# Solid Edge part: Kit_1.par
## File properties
Sűrűség: 0,000 kg/m^3
Pontosság: 0,990
Author: ahadarics
Last saved by: ahadarics
Revision: 76
Username: ahadarics
Dokumentum tartalom típus: 0
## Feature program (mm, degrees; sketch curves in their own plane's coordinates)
base feature "unnamed BaseFeature 1"
thread "unnamed Thread 1"
chamfer "unnamed Chamfer 1"
sketch for "Furat_1" plane through (0, -48.5, 12) normal (0, 0, 1) x-axis (0, 1, 0)
hole "Furat_1" diameter 9.728 finite  ThreadDepth = 7.5 mm
chamfer "Letörés_2" setback 0.7
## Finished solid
Body 1: solid body, 75 faces, 111 edges, 38 vertices, 5 internal voids.
  Faces by surface: plane 27, cone 23, cylinder 20, torus 5
  Edges by curve: circle 67, line 28, spline 12, intersection 4
Bounding box of the edges (mm; curved faces can reach further): 26.800 x 43.000 x 25.400, from (-13.4, -76.25, -13.4) to (13.4, -33.25, 12).
Cylindrical faces by radius (mm): R4 x1, R4.15 x1, R4.28 x1, R4.283 x1, R5.25 x1, R5.55 x1, R6 x2, R7.05 x3, R8.05 x1, R8.1 x1, R8.95 x1, R9.85 x1, R10 x1, R11 x2, R11.1 x1, R13.4 x1
Conical faces (half-angle, radius in mm at the cone's reference point): 0.1788 deg R6.7706 x1, 17.2279 deg R5.55 x1, 19.7315 deg R5.0176 x1, 20 deg R5.909 x2, 21.5244 deg R6.2703 x1, 30 deg R9.9134 x1, 45 deg R4.25 x8, 45 deg R4.983 x1, 45 deg R6.15 x1, 45 deg R7.2 x1, 45 deg R9.475 x1, 45 deg R11 x1, 59 deg R2.1415 x2, 60 deg R10.425 x1
Toroidal faces (ring radius, tube radius in mm): R6.6424 r0.4 x1, R6.85 r0.2 x1, R7.85 r0.2 x1, R7.9 r0.2 x2
Planar faces by outward normal: +x 1, +y 5, +z 2, -x 1, -y 14, oblique 4
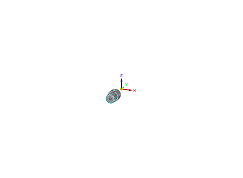
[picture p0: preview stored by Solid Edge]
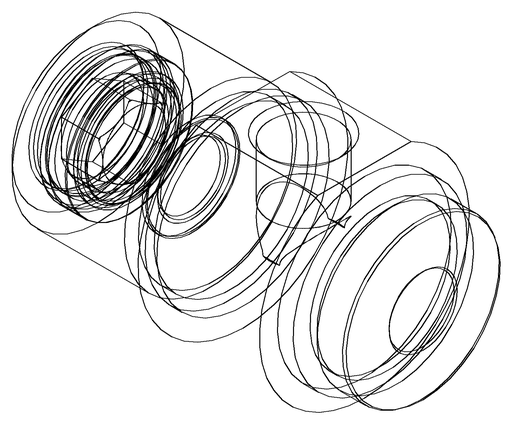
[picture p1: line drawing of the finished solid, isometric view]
